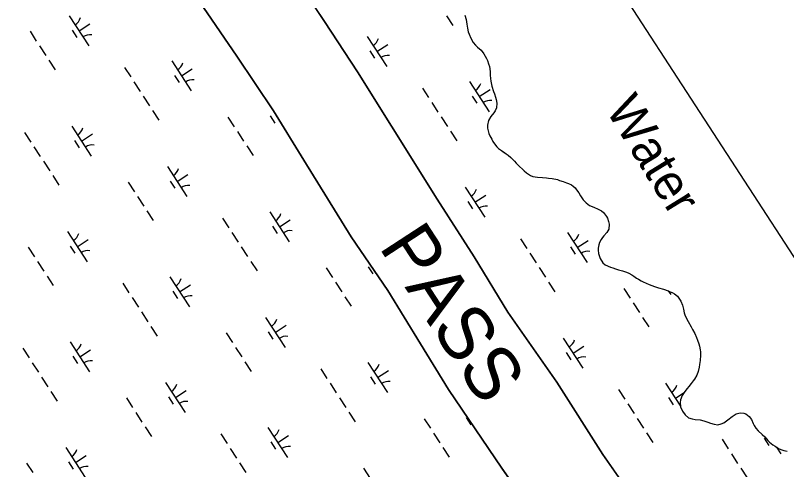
# Model space of a CAD drawing. Extents: x 3953924 to 3974542, y 193747 to 216192.
# Drawn here: x 3966143 to 3967220, y 209558 to 210192 of the extents above; entities that cross this region are included whole.
import ezdxf

# ---------------------------------------------------------------- set-up
doc = ezdxf.new("R2010")
doc.units = 0
for name, color, linetype in [('V-GRID-FRAM', 7, 'Continuous'), ('V-RIVR-IDEN', 7, 'Continuous'), ('V-TOPO-SHOR', 7, 'Continuous'), ('V-WETL-SWMP', 7, 'Continuous')]:
    doc.layers.add(name, color=color, linetype=linetype)

msp = doc.modelspace()

# ---------------------------------------------------------------- linework, layer by layer
at = {"layer": 'V-GRID-FRAM'}
msp.add_lwpolyline([(3964669.3, 213787.9), (3972946, 201072.9), (3966057, 196668.5), (3957950.8, 209463.9), (3964669.3, 213787.9)], dxfattribs=at)
at = {"layer": 'V-TOPO-SHOR'}
for points in [[(3966025.8, 210817.6), (3966080.9, 210726.2), (3966132.9, 210638.5), (3966189.5, 210544.9), (3966250.9, 210442), (3966295.5, 210369.1), (3966335.6, 210308.1), (3966399.9, 210211.6), (3966452.4, 210134.8), (3966503.7, 210058.3), (3966545.9, 209989.5), (3966612, 209882.7), (3966662.9, 209808.1), (3966708.9, 209733.5), (3966747.8, 209669.6), (3966822.4, 209559.9), (3966883.4, 209473.6)], [(3966172.7, 210824.3), (3966218.3, 210740.7), (3966269.3, 210656.8), (3966305, 210597.1), (3966342.1, 210540.3), (3966381, 210474.3), (3966411, 210424.1), (3966461.7, 210346.5), (3966519.7, 210264.8), (3966574.8, 210183.3), (3966620.8, 210113), (3966668.4, 210037.2), (3966732, 209935.1), (3966783.4, 209854.7), (3966830.4, 209777.8), (3966898.9, 209680.2), (3966963.1, 209579.3), (3967011.2, 209510.5), (3967068.3, 209424.1), (3967105.8, 209363.2), (3967136.3, 209315.9), (3967163.4, 209273), (3967201.7, 209202.4), (3967244.9, 209125)], [(3966770.7, 210192.1), (3966772.3, 210185.7), (3966773.4, 210179.3), (3966774.1, 210173.9), (3966775.3, 210168.6), (3966776.5, 210165.3), (3966778.9, 210159.7), (3966782.1, 210154), (3966785.4, 210150), (3966788.3, 210147.3), (3966793.3, 210142.9), (3966797.3, 210138), (3966800.9, 210131.7), (3966802.1, 210128.7)], [(3966802.1, 210128.7), (3966803.8, 210124.2), (3966805, 210120.2), (3966805.8, 210113.6), (3966805.9, 210108.1), (3966806.4, 210103.4), (3966806.9, 210099.9), (3966808.5, 210093.1), (3966810.7, 210085.6), (3966811.9, 210082.4), (3966813.5, 210077.5), (3966814.5, 210074.2), (3966815.2, 210069.3), (3966814.9, 210062.5), (3966813.1, 210058.3), (3966811.1, 210055.6), (3966806.8, 210050.8), (3966803.6, 210045.2), (3966802.1, 210038.7), (3966802.1, 210034.5), (3966804, 210027), (3966805.7, 210023.8), (3966808.2, 210018.9), (3966809.9, 210015.6), (3966811.9, 210012.4), (3966815.4, 210008.3), (3966817.7, 210006), (3966821.6, 210003), (3966824.3, 210001.2), (3966828.5, 209998.5), (3966831.2, 209996.5), (3966834.9, 209993.5), (3966839.9, 209988.5), (3966842.4, 209985.6), (3966847, 209980.9), (3966850.9, 209977), (3966853.2, 209974.9), (3966856.6, 209972.2), (3966862.1, 209968.5), (3966865.6, 209967.1), (3966872.1, 209965.8), (3966878.9, 209965.4), (3966884.6, 209965), (3966887.6, 209964.6), (3966892.5, 209964.2), (3966899.7, 209962.5), (3966902.9, 209961.5), (3966907.9, 209959.8), (3966912.7, 209958.3), (3966915.5, 209957.2), (3966919.4, 209955.1), (3966922, 209953.2), (3966924.4, 209950.9), (3966926.6, 209948.4), (3966929.7, 209944.2), (3966932.1, 209939.8), (3966935.6, 209934.4), (3966939.8, 209930.1), (3966944.7, 209926.6), (3966950.7, 209923.9), (3966956.8, 209921.5), (3966961.4, 209919), (3966964.2, 209916.5), (3966968.1, 209911.3), (3966969.5, 209908.6), (3966971.2, 209904.2), (3966972.1, 209900.2), (3966971.6, 209893.5), (3966969, 209888.9), (3966964.8, 209884.2), (3966962.7, 209881.9), (3966961.1, 209879.2), (3966958.6, 209874.9), (3966957.5, 209871.6), (3966956.5, 209867.1), (3966956.5, 209864), (3966957, 209859.3), (3966959.5, 209852.3), (3966963.4, 209846.6), (3966966.5, 209843.9), (3966973.7, 209840.4), (3966977.2, 209839.3), (3966980.9, 209838.2), (3966984.9, 209836.9), (3966990.8, 209835.3), (3966996.2, 209833.3), (3966999.4, 209831.9), (3967003.9, 209829.7), (3967006.4, 209827.9), (3967010.2, 209825.3), (3967012.8, 209823.5), (3967016.7, 209821.3), (3967019.4, 209820), (3967023.6, 209818), (3967027.9, 209816.4), (3967035.3, 209813.6), (3967040.9, 209811.7), (3967048.1, 209809.7), (3967054.4, 209807.6), (3967057.1, 209806.2), (3967060.2, 209805)], [(3967060.2, 209805), (3967063.4, 209803.2), (3967067.3, 209799.9), (3967070.4, 209795.9), (3967072.3, 209792.9), (3967074.6, 209787.2), (3967075.7, 209781.8), (3967076.9, 209776.6), (3967078.2, 209772.7), (3967082.1, 209764.8), (3967086.3, 209757.4), (3967088.4, 209753.6), (3967091.5, 209748), (3967094, 209742.5), (3967095.5, 209738.7), (3967097.2, 209733.4), (3967098.2, 209730.2), (3967098.9, 209725.3), (3967099.4, 209722.1), (3967099.7, 209717.9), (3967099.1, 209710.3), (3967098.1, 209704.8), (3967097.5, 209701), (3967096.3, 209694.9), (3967094.6, 209689.7), (3967091.3, 209684.3), (3967089.5, 209681.8), (3967086.3, 209678), (3967083.1, 209673.9), (3967080.7, 209671.1), (3967077.6, 209667.1), (3967074.1, 209661.5), (3967071.8, 209655.3), (3967071.2, 209651.8), (3967071.8, 209645.4), (3967074.5, 209639.6), (3967078, 209634.6), (3967082.7, 209630.4), (3967087.9, 209628.8), (3967092.2, 209628.1), (3967098.9, 209627.4), (3967104, 209626.3), (3967110, 209624.3), (3967113.4, 209622.9), (3967118.6, 209621.3), (3967123.9, 209620.7), (3967128.5, 209621.9), (3967132.2, 209623.3), (3967137.8, 209627.6), (3967143.7, 209632.3), (3967149.4, 209635.7), (3967154.7, 209637.3), (3967159.9, 209637), (3967162.9, 209636), (3967167.5, 209632.1), (3967170.5, 209628.1), (3967173, 209622.5), (3967174.3, 209619.7), (3967176.6, 209615.9), (3967180.1, 209612), (3967185.7, 209607), (3967189.2, 209603.6), (3967193.7, 209598.5), (3967196, 209596.2), (3967200.4, 209592.7), (3967203.7, 209590.6), (3967208.3, 209587.6), (3967211.5, 209586.3), (3967216, 209584.8), (3967220.3, 209584)]]:
    msp.add_lwpolyline(points, dxfattribs=at)
at = {"layer": 'V-WETL-SWMP'}
for p, q in [((3966574.8, 210183.3), (3966519.7, 210264.8)), ((3966452.4, 210134.8), (3966399.9, 210211.6)), ((3966218.5, 210191), (3966245.7, 210149.1)), ((3966745, 210191), (3966753.8, 210177.6)), ((3966770.7, 210192.1), (3966772.3, 210185.7)), ((3966232.1, 210170.1), (3966247.2, 210179.9)), ((3966620.8, 210113), (3966574.8, 210183.3)), ((3966772.3, 210185.7), (3966773.4, 210179.3)), ((3966163.7, 210169.4), (3966172.4, 210155.9)), ((3966222.4, 210170.9), (3966228.9, 210160.8)), ((3966773.4, 210179.3), (3966774.1, 210173.9)), ((3966774.1, 210173.9), (3966775.3, 210168.6)), ((3966634.2, 210162.2), (3966661.5, 210120.3)), ((3966775.3, 210168.6), (3966776.5, 210165.3)), ((3966776.5, 210165.3), (3966778.9, 210159.7)), ((3966778.9, 210159.7), (3966782.1, 210154)), ((3966176.8, 210149.2), (3966185.5, 210135.8)), ((3966647.8, 210141.3), (3966662.9, 210151.1)), ((3966782.1, 210154), (3966785.4, 210150)), ((3966785.4, 210150), (3966788.3, 210147.3)), ((3966638.1, 210142.1), (3966644.6, 210132)), ((3966788.3, 210147.3), (3966793.3, 210142.9)), ((3966793.3, 210142.9), (3966797.3, 210138)), ((3966797.3, 210138), (3966800.9, 210131.7)), ((3966189.9, 210129.1), (3966198.6, 210115.7)), ((3966361.4, 210128.1), (3966388.6, 210086.2)), ((3966503.7, 210058.3), (3966452.4, 210134.8)), ((3966800.9, 210131.7), (3966802.1, 210128.7)), ((3966802.1, 210128.7), (3966803.8, 210124.2)), ((3966295.5, 210119.1), (3966304.3, 210105.7)), ((3966375, 210107.1), (3966390.1, 210116.9)), ((3966803.8, 210124.2), (3966805, 210120.2)), ((3966805, 210120.2), (3966805.8, 210113.6)), ((3966365.3, 210107.9), (3966371.8, 210097.9)), ((3966668.4, 210037.2), (3966620.8, 210113)), ((3966805.8, 210113.6), (3966805.9, 210108.1)), ((3966805.9, 210108.1), (3966806.4, 210103.4)), ((3966308.6, 210099), (3966317.4, 210085.6)), ((3966777.1, 210099.2), (3966804.4, 210057.3)), ((3966806.4, 210103.4), (3966806.9, 210099.9)), ((3966806.9, 210099.9), (3966808.5, 210093.1)), ((3966711.3, 210090.3), (3966720, 210076.9)), ((3966790.7, 210078.3), (3966805.8, 210088.1)), ((3966808.5, 210093.1), (3966810.7, 210085.6)), ((3966810.7, 210085.6), (3966811.9, 210082.4)), ((3966321.7, 210078.9), (3966330.5, 210065.5)), ((3966781, 210079.1), (3966787.5, 210069.1)), ((3966811.9, 210082.4), (3966813.5, 210077.5)), ((3966813.5, 210077.5), (3966814.5, 210074.2)), ((3966814.5, 210074.2), (3966815.2, 210069.3)), ((3966494.8, 210071.5), (3966508.7, 210050)), ((3966724.3, 210070.2), (3966733.1, 210056.8)), ((3966814.9, 210062.5), (3966813.1, 210058.3)), ((3966815.2, 210069.3), (3966814.9, 210062.5)), ((3966334.8, 210058.8), (3966343.5, 210045.4)), ((3966498.7, 210051.3), (3966505.2, 210041.3)), ((3966545.9, 209989.5), (3966503.7, 210058.3)), ((3966508.4, 210050.5), (3966508.4, 210050.5)), ((3966806.8, 210050.8), (3966803.6, 210045.2)), ((3966811.1, 210055.6), (3966806.8, 210050.8)), ((3966813.1, 210058.3), (3966811.1, 210055.6)), ((3966440, 210049.8), (3966448.8, 210036.4)), ((3966737.4, 210050.1), (3966746.2, 210036.7)), ((3966803.6, 210045.2), (3966802.1, 210038.7)), ((3966222, 210037.3), (3966249.2, 209995.4)), ((3966453.1, 210029.7), (3966461.8, 210016.3)), ((3966732, 209935.1), (3966668.4, 210037.2)), ((3966750.5, 210030), (3966759.3, 210016.6)), ((3966802.1, 210038.7), (3966802.1, 210034.5)), ((3966802.1, 210034.5), (3966804, 210027)), ((3966156.1, 210028.4), (3966164.9, 210015)), ((3966235.6, 210016.4), (3966250.7, 210026.2)), ((3966804, 210027), (3966805.7, 210023.8)), ((3966805.7, 210023.8), (3966808.2, 210018.9)), ((3966808.2, 210018.9), (3966809.9, 210015.6)), ((3966169.2, 210008.3), (3966178, 209994.9)), ((3966225.9, 210017.2), (3966232.4, 210007.1)), ((3966466.2, 210009.6), (3966474.9, 209996.1)), ((3966809.9, 210015.6), (3966811.9, 210012.4)), ((3966811.9, 210012.4), (3966815.4, 210008.3)), ((3966815.4, 210008.3), (3966817.7, 210006)), ((3966817.7, 210006), (3966821.6, 210003)), ((3966821.6, 210003), (3966824.4, 210001.2)), ((3966824.4, 210001.2), (3966828.5, 209998.5)), ((3966828.5, 209998.5), (3966831.2, 209996.5)), ((3966182.3, 209988.2), (3966191.1, 209974.8)), ((3966612, 209882.7), (3966545.9, 209989.5)), ((3966831.2, 209996.5), (3966834.9, 209993.5)), ((3966834.9, 209993.5), (3966839.9, 209988.5)), ((3966839.9, 209988.5), (3966842.4, 209985.6)), ((3966355.4, 209980.7), (3966382.7, 209938.8)), ((3966842.4, 209985.6), (3966847, 209980.9)), ((3966847, 209980.9), (3966850.9, 209977)), ((3966850.9, 209977), (3966853.2, 209974.9)), ((3966195.4, 209968.1), (3966204.1, 209954.6)), ((3966369, 209959.8), (3966384.1, 209969.6)), ((3966853.2, 209974.9), (3966856.6, 209972.2)), ((3966856.6, 209972.2), (3966862.1, 209968.5)), ((3966862.1, 209968.5), (3966865.6, 209967.1)), ((3966865.6, 209967.1), (3966872.1, 209965.8)), ((3966872.1, 209965.8), (3966878.9, 209965.4)), ((3966878.9, 209965.4), (3966884.6, 209965)), ((3966884.6, 209965), (3966887.6, 209964.6)), ((3966887.6, 209964.6), (3966892.5, 209964.2)), ((3966300.6, 209959), (3966309.4, 209945.6)), ((3966359.3, 209960.6), (3966365.8, 209950.5)), ((3966892.5, 209964.2), (3966899.7, 209962.5)), ((3966899.7, 209962.5), (3966902.9, 209961.5)), ((3966902.9, 209961.5), (3966907.9, 209959.8)), ((3966907.9, 209959.8), (3966912.7, 209958.3)), ((3966912.7, 209958.3), (3966915.5, 209957.2)), ((3966915.5, 209957.2), (3966919.4, 209955.1)), ((3966919.4, 209955.1), (3966922, 209953.2)), ((3966771.1, 209951.9), (3966798.4, 209910)), ((3966922, 209953.2), (3966924.4, 209950.9)), ((3966924.4, 209950.9), (3966926.6, 209948.4)), ((3966926.6, 209948.4), (3966929.7, 209944.2)), ((3966929.7, 209944.2), (3966932.1, 209939.8)), ((3966313.7, 209938.9), (3966322.4, 209925.5)), ((3966783.4, 209854.7), (3966732, 209935.1)), ((3966784.7, 209930.9), (3966799.8, 209940.8)), ((3966932.1, 209939.8), (3966935.6, 209934.4)), ((3966935.6, 209934.4), (3966939.8, 209930.1)), ((3966775, 209931.8), (3966781.5, 209921.7)), ((3966939.8, 209930.1), (3966944.7, 209926.6)), ((3966944.7, 209926.6), (3966950.7, 209923.9)), ((3966950.7, 209923.9), (3966956.8, 209921.5)), ((3966956.8, 209921.5), (3966961.4, 209919)), ((3966326.8, 209918.8), (3966335.5, 209905.4)), ((3966498.3, 209917.8), (3966525.5, 209875.9)), ((3966961.4, 209919), (3966964.2, 209916.5)), ((3966964.2, 209916.5), (3966968.1, 209911.3)), ((3966968.1, 209911.3), (3966969.5, 209908.6)), ((3966432.4, 209908.8), (3966441.2, 209895.4)), ((3966511.9, 209896.8), (3966527, 209906.6)), ((3966969.5, 209908.6), (3966971.2, 209904.2)), ((3966971.2, 209904.2), (3966972.1, 209900.2)), ((3966972.1, 209900.2), (3966971.6, 209893.5)), ((3966216, 209890), (3966243.3, 209848.1)), ((3966502.2, 209897.6), (3966508.7, 209887.6)), ((3966971.6, 209893.5), (3966969, 209888.9)), ((3966229.6, 209869), (3966244.7, 209878.8)), ((3966445.5, 209888.7), (3966454.3, 209875.3)), ((3966662.9, 209808.1), (3966612, 209882.7)), ((3966848.2, 209880), (3966856.9, 209866.6)), ((3966914, 209888.9), (3966941.3, 209847)), ((3966961.1, 209879.2), (3966958.6, 209874.9)), ((3966962.7, 209881.9), (3966961.1, 209879.2)), ((3966964.8, 209884.2), (3966962.7, 209881.9)), ((3966969, 209888.9), (3966964.8, 209884.2)), ((3966161.2, 209868.3), (3966169.9, 209854.9)), ((3966219.9, 209869.8), (3966226.4, 209859.8)), ((3966458.6, 209868.6), (3966467.4, 209855.2)), ((3966917.9, 209868.8), (3966924.4, 209858.7)), ((3966927.6, 209868), (3966942.7, 209877.8)), ((3966957.5, 209871.6), (3966956.5, 209867.1)), ((3966958.6, 209874.9), (3966957.5, 209871.6)), ((3966861.3, 209859.9), (3966870, 209846.5)), ((3966956.5, 209867.1), (3966956.5, 209864)), ((3966956.5, 209864), (3966957, 209859.3)), ((3966957, 209859.3), (3966959.5, 209852.3)), ((3966174.3, 209848.2), (3966183, 209834.8)), ((3966471.7, 209848.5), (3966480.5, 209835.1)), ((3966830.4, 209777.8), (3966783.4, 209854.7)), ((3966959.5, 209852.3), (3966963.4, 209846.6)), ((3966963.4, 209846.6), (3966966.5, 209843.9)), ((3966576.9, 209839.5), (3966585.7, 209826.1)), ((3966635.6, 209841), (3966642.1, 209831)), ((3966874.3, 209839.8), (3966883.1, 209826.4)), ((3966966.5, 209843.9), (3966973.7, 209840.4)), ((3966973.7, 209840.4), (3966977.2, 209839.3)), ((3966977.2, 209839.3), (3966980.9, 209838.2)), ((3966980.9, 209838.2), (3966984.9, 209836.9)), ((3966984.9, 209836.9), (3966990.8, 209835.3)), ((3966990.8, 209835.3), (3966996.2, 209833.3)), ((3966187.4, 209828.1), (3966196.1, 209814.7)), ((3966358.9, 209827), (3966386.1, 209785.1)), ((3966996.2, 209833.3), (3966999.4, 209831.9)), ((3966999.4, 209831.9), (3967003.9, 209829.7)), ((3967003.9, 209829.7), (3967006.4, 209827.9)), ((3967006.4, 209827.9), (3967010.2, 209825.3)), ((3967010.2, 209825.3), (3967012.8, 209823.5)), ((3966293, 209818.1), (3966301.8, 209804.7)), ((3966372.5, 209806.1), (3966387.6, 209815.9)), ((3966590, 209819.3), (3966598.8, 209805.9)), ((3966887.4, 209819.7), (3966896.2, 209806.2)), ((3967012.8, 209823.5), (3967016.7, 209821.3)), ((3967016.7, 209821.3), (3967019.4, 209820)), ((3967019.4, 209820), (3967023.6, 209818)), ((3967023.6, 209818), (3967027.9, 209816.4)), ((3967027.9, 209816.4), (3967035.3, 209813.6)), ((3966362.8, 209806.9), (3966369.3, 209796.8)), ((3966708.9, 209733.5), (3966662.9, 209808.1)), ((3966992.6, 209810.6), (3967001.4, 209797.2)), ((3967035.3, 209813.6), (3967040.9, 209811.7)), ((3967040.9, 209811.7), (3967048.1, 209809.7)), ((3967048.1, 209809.7), (3967054.4, 209807.6)), ((3967054.3, 209807.6), (3967057.9, 209802.1)), ((3967054.4, 209807.6), (3967057.1, 209806.2)), ((3967057.1, 209806.2), (3967060.2, 209805)), ((3967060.2, 209805), (3967063.4, 209803.2)), ((3967063.4, 209803.2), (3967067.3, 209799.9)), ((3966306.1, 209798), (3966314.9, 209784.6)), ((3966603.1, 209799.2), (3966611.8, 209785.8)), ((3967067.3, 209799.9), (3967070.4, 209795.9)), ((3967070.4, 209795.9), (3967072.3, 209792.9)), ((3967072.3, 209792.9), (3967074.6, 209787.2)), ((3967005.7, 209790.5), (3967014.5, 209777.1)), ((3967074.6, 209787.2), (3967075.7, 209781.8)), ((3967075.7, 209781.8), (3967076.9, 209776.6)), ((3966319.2, 209777.9), (3966328, 209764.4)), ((3966898.9, 209680.2), (3966830.4, 209777.8)), ((3967076.9, 209776.6), (3967078.2, 209772.7)), ((3967078.2, 209772.7), (3967082.1, 209764.8)), ((3966492.3, 209770.4), (3966519.6, 209728.5)), ((3967018.8, 209770.4), (3967027.6, 209757)), ((3967082.1, 209764.8), (3967086.3, 209757.4)), ((3966332.3, 209757.7), (3966341.1, 209744.3)), ((3966496.2, 209750.3), (3966502.7, 209740.2)), ((3966505.9, 209749.4), (3966521, 209759.3)), ((3967086.3, 209757.4), (3967088.4, 209753.6)), ((3967088.4, 209753.6), (3967091.5, 209748)), ((3966437.5, 209748.7), (3966446.3, 209735.3)), ((3966908, 209741.6), (3966935.3, 209699.7)), ((3967091.5, 209748), (3967094, 209742.5)), ((3967094, 209742.5), (3967095.5, 209738.7)), ((3967095.5, 209738.7), (3967097.2, 209733.4)), ((3966219.5, 209736.3), (3966246.7, 209694.4)), ((3966450.6, 209728.6), (3966459.4, 209715.2)), ((3966747.8, 209669.6), (3966708.9, 209733.5)), ((3966921.6, 209720.6), (3966936.7, 209730.4)), ((3967097.2, 209733.4), (3967098.2, 209730.2)), ((3967098.2, 209730.2), (3967098.9, 209725.3)), ((3966153.6, 209727.3), (3966162.4, 209713.9)), ((3966233.1, 209715.3), (3966248.2, 209725.1)), ((3966911.9, 209721.4), (3966918.4, 209711.4)), ((3967098.9, 209725.3), (3967099.4, 209722.1)), ((3967099.7, 209717.9), (3967099.1, 209710.3)), ((3967099.4, 209722.1), (3967099.7, 209717.9)), ((3966166.7, 209707.2), (3966175.5, 209693.8)), ((3966223.4, 209716.1), (3966229.9, 209706.1)), ((3966463.7, 209708.5), (3966472.4, 209695.1)), ((3966635.2, 209707.4), (3966662.5, 209665.5)), ((3967099.1, 209710.3), (3967098.1, 209704.8)), ((3966569.4, 209698.5), (3966578.1, 209685.1)), ((3966648.8, 209686.5), (3966663.9, 209696.3)), ((3967097.5, 209701), (3967096.3, 209694.9)), ((3967098.1, 209704.8), (3967097.5, 209701)), ((3966179.8, 209687.1), (3966188.6, 209673.7)), ((3966639.1, 209687.3), (3966645.6, 209677.2)), ((3967094.6, 209689.7), (3967091.3, 209684.3)), ((3967096.3, 209694.9), (3967094.6, 209689.7)), ((3966352.9, 209679.7), (3966380.2, 209637.7)), ((3966582.4, 209678.4), (3966591.2, 209665)), ((3966963.1, 209579.3), (3966898.9, 209680.2)), ((3967050.9, 209678.6), (3967071.7, 209646.6)), ((3967083.1, 209673.9), (3967080.7, 209671.1)), ((3967086.3, 209678), (3967083.1, 209673.9)), ((3967089.5, 209681.8), (3967086.3, 209678)), ((3967091.3, 209684.3), (3967089.5, 209681.8)), ((3966192.9, 209667), (3966201.6, 209653.6)), ((3966366.5, 209658.7), (3966381.6, 209668.5)), ((3966822.4, 209559.9), (3966747.8, 209669.6)), ((3966985.1, 209669.7), (3966993.8, 209656.3)), ((3967064.5, 209657.7), (3967076.6, 209665.5)), ((3967077.6, 209667.1), (3967074.1, 209661.5)), ((3967080.7, 209671.1), (3967077.6, 209667.1)), ((3966298.1, 209658), (3966306.9, 209644.6)), ((3966356.8, 209659.5), (3966363.3, 209649.5)), ((3966595.5, 209658.3), (3966604.3, 209644.9)), ((3967054.8, 209658.5), (3967061.3, 209648.4)), ((3967071.8, 209655.3), (3967071.2, 209651.8)), ((3967074.1, 209661.5), (3967071.8, 209655.3)), ((3966998.2, 209649.6), (3967006.9, 209636.1)), ((3967071.2, 209651.8), (3967071.8, 209645.4)), ((3967071.8, 209645.4), (3967074.5, 209639.6)), ((3966311.2, 209637.9), (3966319.9, 209624.4)), ((3966608.6, 209638.2), (3966617.4, 209624.8)), ((3967074.5, 209639.6), (3967078, 209634.6)), ((3967078, 209634.6), (3967082.7, 209630.4)), ((3967137.8, 209627.6), (3967143.7, 209632.3)), ((3967143.7, 209632.3), (3967149.4, 209635.7)), ((3967149.4, 209635.7), (3967154.7, 209637.3)), ((3967154.7, 209637.3), (3967159.9, 209637)), ((3967159.9, 209637), (3967162.9, 209636)), ((3967162.9, 209636), (3967167.5, 209632.1)), ((3967167.5, 209632.1), (3967170.5, 209628.1)), ((3966713.8, 209629.1), (3966722.6, 209615.7)), ((3966772.5, 209630.7), (3966779, 209620.6)), ((3967011.3, 209629.4), (3967020, 209616)), ((3967082.7, 209630.4), (3967087.9, 209628.8)), ((3967087.9, 209628.8), (3967092.2, 209628.1)), ((3967092.2, 209628.1), (3967098.9, 209627.4)), ((3967098.9, 209627.4), (3967104, 209626.3)), ((3967104, 209626.3), (3967110, 209624.3)), ((3967110, 209624.3), (3967113.4, 209622.9)), ((3967113.4, 209622.9), (3967118.6, 209621.3)), ((3967118.6, 209621.3), (3967123.9, 209620.7)), ((3967123.9, 209620.7), (3967128.5, 209621.9)), ((3967128.5, 209621.9), (3967132.2, 209623.3)), ((3967132.2, 209623.3), (3967137.8, 209627.6)), ((3967170.5, 209628.1), (3967172.9, 209622.5)), ((3967172.9, 209622.5), (3967174.3, 209619.7)), ((3966324.3, 209617.7), (3966333, 209604.3)), ((3966495.8, 209616.7), (3966523, 209574.8)), ((3967024.3, 209609.3), (3967033.1, 209595.9)), ((3967174.3, 209619.7), (3967176.6, 209615.9)), ((3967176.6, 209615.9), (3967180.1, 209612)), ((3967180.1, 209612), (3967185.7, 209607)), ((3966430, 209607.8), (3966438.7, 209594.3)), ((3966509.4, 209595.7), (3966524.5, 209605.6)), ((3966726.9, 209609), (3966735.7, 209595.6)), ((3967129.6, 209600.3), (3967138.3, 209586.9)), ((3967185.7, 209607), (3967189.2, 209603.6)), ((3967188.2, 209601.9), (3967194.8, 209591.8)), ((3967189.2, 209603.6), (3967193.7, 209598.5)), ((3967193.7, 209598.5), (3967196, 209596.2)), ((3966213.5, 209588.9), (3966240.8, 209547)), ((3966443, 209587.6), (3966451.8, 209574.2)), ((3966499.7, 209596.6), (3966506.2, 209586.5)), ((3966740, 209588.9), (3966748.8, 209575.5)), ((3967196, 209596.2), (3967200.4, 209592.7)), ((3967200.4, 209592.7), (3967203.7, 209590.6)), ((3967203.7, 209590.6), (3967208.3, 209587.6)), ((3967205.6, 209589.3), (3967211.6, 209580.1)), ((3966227.1, 209568), (3966242.2, 209577.8)), ((3967011.2, 209510.5), (3966963.1, 209579.3)), ((3967142.6, 209580.2), (3967151.4, 209566.8)), ((3967208.3, 209587.6), (3967211.5, 209586.3)), ((3967211.5, 209586.3), (3967216, 209584.8)), ((3967216, 209584.8), (3967220.3, 209584)), ((3966158.7, 209567.2), (3966167.4, 209553.8)), ((3966217.4, 209568.8), (3966223.9, 209558.7)), ((3966456.1, 209567.5), (3966464.9, 209554.1)), ((3966629.2, 209560.1), (3966656.5, 209518.2)), ((3966883.4, 209473.6), (3966822.4, 209559.9)), ((3967155.7, 209560.1), (3967164.5, 209546.7))]:
    msp.add_line(p, q, dxfattribs=at)
for centre, start, end in [((3966217.2, 210193.4), 302.2901, 343.8338), ((3966247.4, 210147.1), 82.2901, 123.8337), ((3966633, 210164.5), 302.2901, 343.8338), ((3966663.1, 210118.2), 82.2901, 123.8337), ((3966360.1, 210130.4), 302.2901, 343.8338), ((3966390.3, 210084.1), 82.2901, 123.8337), ((3966775.8, 210101.6), 302.2901, 343.8338), ((3966806, 210055.3), 82.2901, 123.8337), ((3966493.6, 210073.8), 302.2901, 303.0948), ((3966220.7, 210039.7), 302.2901, 343.8338), ((3966250.9, 209993.4), 82.2901, 123.8337), ((3966354.1, 209983), 302.2901, 343.8338), ((3966384.3, 209936.7), 82.2901, 123.8337), ((3966769.9, 209954.2), 302.2901, 343.8338), ((3966800, 209907.9), 82.2901, 123.8337), ((3966497, 209920.1), 302.2901, 343.8338), ((3966527.2, 209873.8), 82.2901, 123.8337), ((3966214.7, 209892.3), 302.2901, 343.8338), ((3966912.8, 209891.3), 302.2901, 343.8338), ((3966244.9, 209846), 82.2901, 123.8337), ((3966942.9, 209845), 82.2901, 123.8337), ((3966357.6, 209829.3), 302.2901, 343.8338), ((3966387.8, 209783), 82.2901, 123.8337), ((3966491.1, 209772.7), 302.2901, 343.8338), ((3966521.2, 209726.4), 82.2901, 123.8337), ((3966906.8, 209743.9), 302.2901, 343.8338), ((3966218.2, 209738.6), 302.2901, 343.8338), ((3966248.4, 209692.3), 82.2901, 123.8337), ((3966936.9, 209697.6), 82.2901, 123.8337), ((3966633.9, 209709.8), 302.2901, 343.8338), ((3966351.6, 209682), 302.2901, 343.8338), ((3966664.1, 209663.5), 82.2901, 123.8337), ((3967049.7, 209680.9), 302.2901, 343.8338), ((3966381.8, 209635.7), 82.2901, 123.8337), ((3967079.8, 209634.6), 118.5497, 123.8337), ((3966494.5, 209619), 302.2901, 343.8338), ((3966524.7, 209572.7), 82.2901, 123.8337), ((3966212.2, 209591.2), 302.2901, 343.8338), ((3966242.4, 209544.9), 82.2901, 123.8337)]:
    msp.add_arc(centre, 17.6, start, end, dxfattribs=at)

# ---------------------------------------------------------------- texts
at = {"layer": 'V-RIVR-IDEN'}
for s, height, rotation, p in [('Water', 50, 301.6613, (3966966.1, 210060.6)), ('PASS', 75, 303.0607, (3966649.7, 209868.9))]:
    msp.add_text(s, height=height, rotation=rotation, dxfattribs=at).set_placement(p)

doc.saveas('drawing.dxf')
